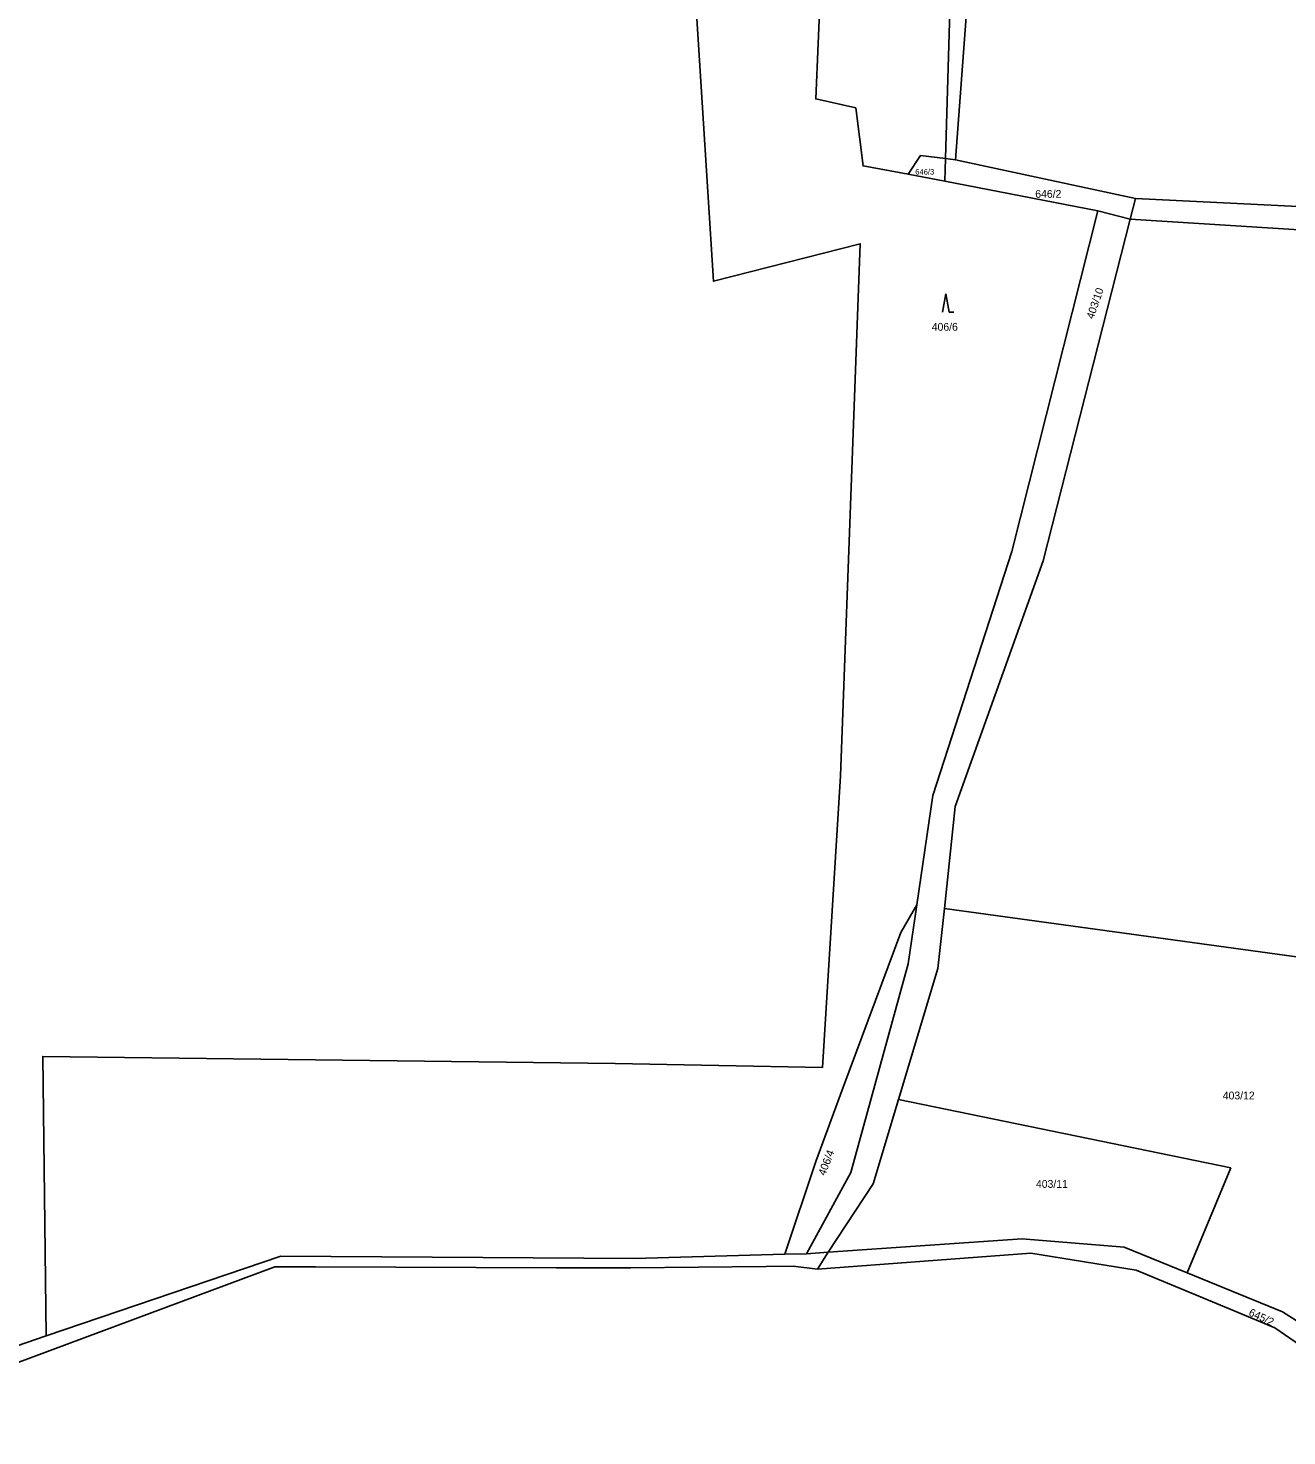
# Model space of a CAD drawing. Extents: x -744566 to -741843, y -1128407 to -1126744.
# Drawn here: x -744236.2 to -743962, y -1127580.1 to -1127273.4 of the extents above; entities that cross this region are included whole.
import ezdxf

# ---------------------------------------------------------------- set-up
doc = ezdxf.new("R2010")
doc.units = 0
for name, color, linetype in [('Hranice parcel', 7, 'Continuous'), ('Parcelní čísla', 7, 'Continuous'), ('Značky kultur', 7, 'Continuous')]:
    doc.layers.add(name, color=color, linetype=linetype)

msp = doc.modelspace()

# ---------------------------------------------------------------- linework, layer by layer
at = {"layer": 'Hranice parcel'}
for p, q in [((-744036.37, -1127301.78), (-744036.49, -1127306.74)), ((-744034.18, -1127302.06), (-744036.37, -1127301.78)), ((-744034.18, -1127302.06), (-743994.91, -1127310.47)), ((-744036.49, -1127306.74), (-744044.5, -1127305.2)), ((-744036.49, -1127306.74), (-744003.15, -1127313.14)), ((-743994.91, -1127310.47), (-743996.07, -1127315.02)), ((-743994.91, -1127310.47), (-743898.15, -1127315.31)), ((-743996.07, -1127315.02), (-744003.15, -1127313.14)), ((-744066.61, -1127540.41), (-744071.31, -1127540.54)), ((-744066.61, -1127540.41), (-744061.89, -1127540.09)), ((-744064.25, -1127543.77), (-744061.89, -1127540.09)), ((-744064.25, -1127543.77), (-744017.72, -1127540.31)), ((-744223.95, -1127558.72), (-744182.46, -1127543.26)), ((-744182.46, -1127543.26), (-744173.58, -1127543.29)), ((-744173.58, -1127543.29), (-744121.06, -1127543.47)), ((-744121.06, -1127543.47), (-744104.89, -1127543.52)), ((-744104.89, -1127543.52), (-744075.38, -1127543.22)), ((-744075.38, -1127543.22), (-744069.49, -1127543.16)), ((-744069.49, -1127543.16), (-744064.25, -1127543.77)), ((-744239.37, -1127564.46), (-744223.95, -1127558.72))]:
    msp.add_line(p, q, dxfattribs=at)
for points in [[(-744036.37, -1127301.78), (-744035.31, -1127267.07), (-744021.71, -1127201.91)], [(-744017.53, -1127201.77), (-744030.19, -1127248.42), (-744034.18, -1127302.06)], [(-744232.26, -1127558.32), (-744232.99, -1127497.42), (-744108.28, -1127499), (-744063.15, -1127499.85), (-744059.18, -1127436.28), (-744054.92, -1127320.35), (-744086.9, -1127328.53), (-744091.8, -1127250.55), (-744074.74, -1127255.35), (-744063.54, -1127264.6), (-744064.61, -1127288.79), (-744055.9, -1127290.74), (-744054.3, -1127303.37), (-744044.5, -1127305.2)], [(-744044.5, -1127305.2), (-744041.78, -1127301.09), (-744036.37, -1127301.78)], [(-744003.15, -1127313.14), (-744021.89, -1127387.43), (-744039.08, -1127440.6), (-744042.56, -1127464.39)], [(-743996.07, -1127315.02), (-744015.09, -1127389.44), (-744034.2, -1127442.97), (-744036.57, -1127465.21)], [(-743812.42, -1127332.86), (-743886.76, -1127321.92), (-743996.07, -1127315.02)], [(-744036.57, -1127465.21), (-743930.75, -1127479.74), (-743917.88, -1127448.05), (-743897.73, -1127460.48)], [(-744042.56, -1127464.39), (-744046.07, -1127470.44), (-744058.7, -1127504.33), (-744064.57, -1127520.32), (-744071.31, -1127540.54)], [(-744042.56, -1127464.39), (-744044.44, -1127477.28), (-744056.94, -1127522.7), (-744066.61, -1127540.41)], [(-744046.58, -1127506.83), (-744037.97, -1127478.28), (-744036.57, -1127465.21)], [(-744061.89, -1127540.09), (-744052.11, -1127525.18), (-744046.58, -1127506.83)], [(-743983.71, -1127544.61), (-743974.21, -1127521.73), (-744046.58, -1127506.83)], [(-743983.71, -1127544.61), (-743997.44, -1127539.01), (-744019.6, -1127537.15), (-744061.89, -1127540.09)], [(-744071.31, -1127540.54), (-744104.13, -1127541.44), (-744181.13, -1127540.94), (-744232.26, -1127558.32)], [(-744017.72, -1127540.31), (-743994.77, -1127543.98), (-743973.44, -1127552.88)], [(-743952.02, -1127560), (-743962.9, -1127553.1), (-743983.71, -1127544.61)], [(-743973.44, -1127552.88), (-743964.58, -1127556.58), (-743951.49, -1127565.55)], [(-744460.69, -1127573.57), (-744426.24, -1127580.1), (-744395.07, -1127577.86), (-744365.75, -1127572.94), (-744325.02, -1127570.79), (-744283.5, -1127570.77), (-744240.92, -1127561.26), (-744232.26, -1127558.32)]]:
    msp.add_lwpolyline(points, dxfattribs=at)
at = {"layer": 'Značky kultur'}
for p, q in [((-744036.25, -1127331.26), (-744037, -1127335.26)), ((-744035.5, -1127335.26), (-744036.25, -1127331.26)), ((-744035.5, -1127335.26), (-744034.504, -1127335.26))]:
    msp.add_line(p, q, dxfattribs=at)

# ---------------------------------------------------------------- texts
at = {"layer": 'Parcelní čísla'}
for s, height, p in [('646/3', 1.19, (-744042.91, -1127305.265)), ('646/2', 1.7, (-744016.78, -1127310.33)), ('406/6', 1.7, (-744039.33, -1127339.3)), ('403/12', 1.7, (-743975.93, -1127506.79)), ('403/11', 1.7, (-744016.63, -1127526.06))]:
    msp.add_text(s, height=height, dxfattribs=at).set_placement(p)
for s, rotation, p in [('403/10', 71, (-744004.106, -1127336.876)), ('406/4', 69, (-744062.556, -1127523.524)), ('645/2', 335, (-743970.442, -1127553.798))]:
    msp.add_text(s, height=1.7, rotation=rotation, dxfattribs=at).set_placement(p)

doc.saveas('drawing.dxf')
